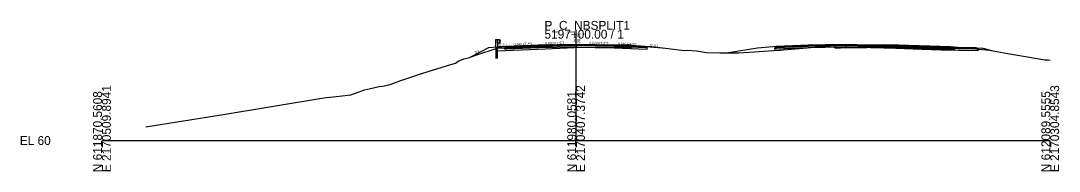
# Model space of a CAD drawing. Extents: x -26 to 1303, y -3010 to 12038.
# Drawn here: x -25.7 to 302.8, y 11990.3 to 12037.8 of the extents above; entities that cross this region are included whole.
import ezdxf

# ---------------------------------------------------------------- set-up
doc = ezdxf.new("R2010")
doc.units = 0
for name, color, linetype in [('RD_GPK_XS_Cell', 7, 'Continuous'), ('RD_PD_Final_TrvlWay', 7, 'Continuous'), ('RD_XS_Base', 7, 'Continuous'), ('RD_XS_ExGround', 7, 'Continuous'), ('RD_XS_ExPaveRet', 7, 'Continuous'), ('RD_XS_GR', 7, 'Continuous'), ('RD_XS_Greenside', 7, 'Continuous'), ('RD_XS_Pave', 7, 'Continuous'), ('RD_XS_PaveOvlay_CP', 7, 'Continuous'), ('RD_XS_TieSlope', 7, 'Continuous'), ('RD_XS_TX_Elev_EX', 7, 'Continuous'), ('RD_XS_TX_Elev_PR', 7, 'Continuous'), ('RD_XS_TX_ShdSlope', 7, 'Continuous'), ('RD_XS_TX_Slope', 7, 'Continuous')]:
    doc.layers.add(name, color=color, linetype=linetype)

msp = doc.modelspace()

# ---------------------------------------------------------------- linework, layer by layer
at = {"layer": 'RD_GPK_XS_Cell'}
for p, q in [((150, 12000), (150, 12035)), ((0, 12000), (150, 12000)), ((150, 12000), (300, 12000))]:
    msp.add_line(p, q, dxfattribs=at)
at = {"layer": 'RD_PD_Final_TrvlWay'}
for p, q in [((125.14, 12029.49), (124.64, 12029.45)), ((124.64, 12029.45), (124.64, 12025.88)), ((125.14, 12025.88), (125.14, 12029.49))]:
    msp.add_line(p, q, dxfattribs=at)
at = {"layer": 'RD_XS_Base'}
for p, q in [((127.5, 12029.38), (128, 12029.4)), ((127.5, 12028.88), (127.5, 12029.38)), ((127.5, 12029.38), (127.5, 12029.38)), ((128, 12028.9), (127.5, 12028.88)), ((127.5, 12028.88), (127.5, 12028.88)), ((127.5, 12028.88), (127.5, 12028.88)), ((128, 12029.4), (138, 12029.8)), ((128, 12029.4), (128, 12029.4)), ((138, 12029.3), (128, 12028.9)), ((128, 12028.9), (128, 12028.9)), ((138, 12029.8), (150, 12030.04)), ((138, 12029.8), (138, 12029.8)), ((150, 12029.54), (138, 12029.3)), ((138, 12029.3), (138, 12029.3)), ((150, 12030.04), (150, 12030.2)), ((150, 12030.2), (150, 12029.54)), ((150, 12030.04), (150, 12029.54)), ((162, 12029.8), (150, 12030.04)), ((150, 12030.04), (150, 12030.04)), ((150, 12029.54), (150, 12029.54)), ((150, 12029.54), (150, 12029.54)), ((150, 12029.54), (162, 12029.3)), ((172, 12029.4), (162, 12029.8)), ((162, 12029.3), (172.5, 12028.88)), ((164, 12029.72), (164, 12029.72)), ((164, 12029.22), (164, 12029.22)), ((172.5, 12029.38), (172, 12029.4)), ((172, 12029.4), (172, 12029.4)), ((172.5, 12028.88), (172.5, 12029.38)), ((172.5, 12029.38), (172.5, 12029.38)), ((172.5, 12028.88), (172.5, 12028.88)), ((172.5, 12028.88), (172.5, 12028.88)), ((212.86, 12029.38), (213.25, 12029.4)), ((212.86, 12029.27), (212.86, 12029.38)), ((212.86, 12028.88), (212.86, 12029.27)), ((213.25, 12028.9), (212.86, 12028.88)), ((213.25, 12029.4), (213.36, 12029.4)), ((213.36, 12028.9), (213.25, 12028.9)), ((213.36, 12029.4), (220.94, 12029.71)), ((220.94, 12029.21), (213.36, 12028.9)), ((220.94, 12029.71), (223.36, 12029.8)), ((223.36, 12029.3), (220.94, 12029.21)), ((223.36, 12029.8), (228.76, 12029.91)), ((228.76, 12029.41), (223.36, 12029.3)), ((228.76, 12029.91), (235.36, 12030.04)), ((235.36, 12029.54), (228.76, 12029.41)), ((235.36, 12030.16), (235.36, 12030.2)), ((235.36, 12030.2), (235.36, 12030.01)), ((235.36, 12030.04), (235.36, 12030.16)), ((235.36, 12030.04), (235.36, 12030.04)), ((238.87, 12029.97), (235.36, 12030.04)), ((235.36, 12030.04), (235.36, 12030.04)), ((235.36, 12030.04), (235.36, 12029.9)), ((235.36, 12030.01), (235.36, 12029.54)), ((235.36, 12029.9), (235.36, 12029.54)), ((235.36, 12029.54), (238.87, 12029.47)), ((247.36, 12029.8), (238.87, 12029.97)), ((238.87, 12029.47), (247.36, 12029.3)), ((251.11, 12029.66), (247.36, 12029.8)), ((247.36, 12029.3), (251.11, 12029.16)), ((259.37, 12029.33), (251.11, 12029.66)), ((251.11, 12029.16), (259.37, 12028.83)), ((265.17, 12029.21), (259.37, 12029.33)), ((259.37, 12028.83), (265.34, 12028.71)), ((276.67, 12028.98), (265.17, 12029.21)), ((265.34, 12028.71), (277.17, 12028.47)), ((276.84, 12028.98), (276.67, 12028.98)), ((277.17, 12028.97), (276.84, 12028.98)), ((277.17, 12028.79), (277.17, 12028.97)), ((277.17, 12028.47), (277.17, 12028.79))]:
    msp.add_line(p, q, dxfattribs=at)
at = {"layer": 'RD_XS_ExGround'}
msp.add_lwpolyline([(13.83, 12004.3), (37.72, 12008.08), (70.17, 12013.47), (75, 12014.04), (78.77, 12014.48), (80.21, 12014.96), (83.07, 12016.05), (84.92, 12016.48), (87.72, 12017.07), (88.89, 12017.23), (91.14, 12017.73), (94.19, 12018.84), (98.32, 12020.24), (101.09, 12021.2), (101.19, 12021.2), (104.83, 12022.32), (108.64, 12023.52), (109.29, 12023.75), (111.88, 12024.47), (112.64, 12025.04), (114.44, 12025.83), (115.91, 12026.14), (118, 12026.91), (125.01, 12029.15), (140.16, 12029.77), (151.86, 12030.25), (161.97, 12030.16), (167.52, 12030.1), (171.81, 12029.79), (175.64, 12029.5), (180.84, 12028.83), (184.15, 12028.5), (185.23, 12028.57), (188.07, 12028.36), (191.22, 12027.79), (195.47, 12027.75), (201.42, 12027.67), (206.46, 12028.03), (212.45, 12028.41), (214.01, 12028.51), (214.64, 12028.58), (215.48, 12028.63), (231.89, 12030), (239.22, 12030.13), (247.19, 12030.27), (269.5, 12029.54), (269.63, 12029.53), (269.71, 12029.52), (269.85, 12029.51), (270.37, 12029.47), (280.92, 12028.54), (281.95, 12028.33), (286.58, 12027.5), (292.13, 12026.57), (298.33, 12025.5), (299.34, 12025.48), (300, 12025.37)], dxfattribs=at)
at = {"layer": 'RD_XS_ExPaveRet'}
for p, q in [((140.16, 12029.77), (125.01, 12029.15)), ((151.86, 12030.25), (140.16, 12029.77)), ((161.97, 12030.16), (151.86, 12030.25)), ((167.52, 12030.1), (161.97, 12030.16)), ((233.66, 12030.03), (231.89, 12030)), ((239.22, 12030.13), (233.66, 12030.03)), ((269.63, 12029.53), (269.5, 12029.54))]:
    msp.add_line(p, q, dxfattribs=at)
for points in [[(161.97, 12030.16), (151.86, 12030.25), (151.86, 12030.25), (151.86, 12030.25), (140.16, 12029.77), (140.16, 12029.77), (125.01, 12029.15), (125.01, 12028.4), (125.01, 12028.4), (140.16, 12029.02), (140.16, 12029.02), (151.86, 12029.5), (151.86, 12029.5), (151.86, 12029.5), (161.97, 12029.41), (161.97, 12029.41), (167.52, 12029.35), (167.52, 12029.35), (167.52, 12030.1), (161.97, 12030.16), (161.97, 12030.16)], [(125.01, 12029.15), (125.01, 12028.4), (140.16, 12029.02), (151.86, 12029.5), (161.97, 12029.41), (167.52, 12029.35), (167.52, 12030.1)], [(269.63, 12029.53), (269.63, 12029.53), (269.63, 12029.4), (269.63, 12028.78), (269.63, 12028.78), (269.63, 12028.78), (268.87, 12028.81), (268.42, 12028.82), (251.96, 12029.36), (247.19, 12029.52), (241.96, 12029.43), (239.22, 12029.38), (233.66, 12029.28), (231.89, 12029.25), (231.89, 12029.25), (231.89, 12029.5), (231.89, 12030), (231.89, 12030), (233.66, 12030.03), (239.22, 12030.13), (241.96, 12030.18), (247.19, 12030.27), (251.96, 12030.11), (268.42, 12029.57), (268.87, 12029.56), (269.63, 12029.53), (269.63, 12029.53)], [(231.89, 12030), (231.89, 12029.5), (231.89, 12029.25), (233.66, 12029.28), (239.22, 12029.38), (241.96, 12029.43), (247.19, 12029.52), (251.96, 12029.36), (268.42, 12028.82), (268.87, 12028.81), (269.63, 12028.78), (269.63, 12028.78), (269.63, 12029.4), (269.63, 12029.53), (269.63, 12029.53)], [(269.5, 12029.54), (268.42, 12029.57), (251.96, 12030.11), (247.19, 12030.27), (241.96, 12030.18), (239.22, 12030.13)]]:
    msp.add_lwpolyline(points, dxfattribs=at)
at = {"layer": 'RD_XS_GR'}
for points in [[(125.14, 12031.88), (125.14, 12029.49), (124.64, 12029.45), (124.64, 12031.88), (124.89, 12031.88), (125.14, 12031.88)], [(125.81, 12031.88), (125.81, 12030.72), (125.14, 12030.72), (125.14, 12031.88), (125.81, 12031.88)], [(126.08, 12031.59), (125.81, 12031.88), (125.81, 12030.72), (125.81, 12030.72), (125.81, 12030.72), (126.08, 12031.01), (126.08, 12031.01), (125.81, 12031.3), (125.81, 12031.3), (126.08, 12031.59), (126.08, 12031.59)]]:
    msp.add_lwpolyline(points, dxfattribs=at)
at = {"layer": 'RD_XS_Greenside'}
for p, q in [((122.33, 12029.26), (116.57, 12026.38)), ((207.36, 12029.24), (198.2, 12027.71)), ((278.67, 12029.14), (281.49, 12028.43))]:
    msp.add_line(p, q, dxfattribs=at)
at = {"layer": 'RD_XS_Pave'}
for p, q in [((138, 12030.12), (128, 12029.72)), ((138, 12029.96), (128, 12029.56)), ((128, 12029.56), (138, 12029.96)), ((128, 12029.4), (138, 12029.8)), ((128, 12029.72), (128, 12029.72)), ((128, 12029.72), (128, 12029.56)), ((128, 12029.56), (128, 12029.56)), ((128, 12029.56), (128, 12029.4)), ((128, 12029.56), (128, 12029.56)), ((128, 12029.56), (128, 12029.56)), ((128, 12029.4), (128, 12029.4)), ((128, 12029.4), (128, 12029.4)), ((150, 12030.36), (138, 12030.12)), ((150, 12030.2), (138, 12029.96)), ((138, 12029.96), (150, 12030.2)), ((138, 12030.12), (138, 12030.12)), ((138, 12029.8), (150, 12030.04)), ((138, 12029.96), (138, 12029.96)), ((138, 12029.96), (138, 12029.96)), ((138, 12029.8), (138, 12029.8)), ((162, 12030.12), (150, 12030.36)), ((150, 12030.04), (150, 12030.2)), ((150, 12030.2), (162, 12029.96)), ((162, 12029.96), (150, 12030.2)), ((150, 12030.2), (150, 12030.04)), ((150, 12030.04), (150, 12030.04)), ((150, 12030.04), (150, 12030.04)), ((150, 12030.04), (162, 12029.8)), ((172, 12029.72), (162, 12030.12)), ((162, 12029.96), (172, 12029.56)), ((172, 12029.56), (162, 12029.96)), ((162, 12029.8), (172, 12029.4)), ((164, 12030.04), (164, 12030.04)), ((164, 12029.88), (164, 12029.88)), ((164, 12029.88), (164, 12029.88)), ((164, 12029.72), (164, 12029.72)), ((172, 12029.56), (172, 12029.72)), ((172, 12029.72), (172, 12029.72)), ((172, 12029.56), (172, 12029.56)), ((172, 12029.56), (172, 12029.56)), ((172, 12029.4), (172, 12029.56)), ((172, 12029.56), (172, 12029.56)), ((172, 12029.4), (172, 12029.4)), ((172, 12029.4), (172, 12029.4)), ((220.94, 12030.03), (213.36, 12029.72)), ((220.94, 12029.87), (213.36, 12029.56)), ((213.36, 12029.56), (220.94, 12029.87)), ((213.36, 12029.72), (213.36, 12029.69)), ((213.36, 12029.4), (220.94, 12029.71)), ((213.36, 12029.69), (213.36, 12029.56)), ((213.36, 12029.56), (213.36, 12029.53)), ((213.36, 12029.53), (213.36, 12029.4)), ((223.36, 12030.12), (220.94, 12030.03)), ((223.36, 12029.96), (220.94, 12029.87)), ((220.94, 12029.87), (223.36, 12029.96)), ((220.94, 12029.71), (223.36, 12029.8)), ((228.76, 12030.23), (223.36, 12030.12)), ((228.76, 12030.07), (223.36, 12029.96)), ((223.36, 12029.96), (228.76, 12030.07)), ((223.36, 12029.8), (228.76, 12029.91)), ((235.36, 12030.36), (228.76, 12030.23)), ((235.36, 12030.2), (228.76, 12030.07)), ((228.76, 12030.07), (235.36, 12030.2)), ((228.76, 12029.91), (235.36, 12030.04)), ((238.87, 12030.29), (235.36, 12030.36)), ((235.36, 12030.16), (235.36, 12030.2)), ((235.36, 12030.2), (238.87, 12030.13)), ((238.87, 12030.13), (235.36, 12030.2)), ((235.36, 12030.2), (235.36, 12030.2)), ((235.36, 12030.2), (235.36, 12030.2)), ((235.36, 12030.2), (235.36, 12030.16)), ((235.36, 12030.04), (235.36, 12030.16)), ((235.36, 12030.16), (235.36, 12030.04)), ((235.36, 12030.04), (235.36, 12030.04)), ((235.36, 12030.04), (235.36, 12030.04)), ((235.36, 12030.04), (238.87, 12029.97)), ((247.36, 12030.12), (238.87, 12030.29)), ((238.87, 12030.13), (247.36, 12029.96)), ((247.36, 12029.96), (238.87, 12030.13)), ((238.87, 12029.97), (247.36, 12029.8)), ((251.11, 12029.97), (247.36, 12030.12)), ((247.36, 12029.96), (251.11, 12029.81)), ((251.11, 12029.81), (247.36, 12029.96)), ((247.36, 12029.8), (251.11, 12029.66)), ((259.37, 12029.64), (251.11, 12029.97)), ((251.11, 12029.81), (259.37, 12029.48)), ((259.37, 12029.48), (251.11, 12029.81)), ((251.11, 12029.66), (259.37, 12029.33)), ((265.17, 12029.53), (259.37, 12029.64)), ((259.37, 12029.48), (265.17, 12029.37)), ((265.17, 12029.37), (259.37, 12029.48)), ((259.37, 12029.33), (265.17, 12029.21)), ((276.67, 12029.3), (265.17, 12029.53)), ((265.17, 12029.37), (276.67, 12029.14)), ((276.67, 12029.14), (265.17, 12029.37)), ((265.17, 12029.21), (276.67, 12028.98)), ((276.67, 12029.24), (276.67, 12029.3)), ((276.67, 12029.14), (276.67, 12029.24)), ((276.67, 12029.08), (276.67, 12029.14)), ((276.67, 12028.98), (276.67, 12029.08))]:
    msp.add_line(p, q, dxfattribs=at)
at = {"layer": 'RD_XS_PaveOvlay_CP'}
for p, q in [((128, 12029.72), (138, 12030.12)), ((138, 12030.12), (150, 12030.36)), ((150, 12030.36), (162, 12030.12)), ((162, 12030.12), (172, 12029.72)), ((220.94, 12030.03), (213.36, 12029.72)), ((223.36, 12030.12), (220.94, 12030.03)), ((228.76, 12030.23), (223.36, 12030.12)), ((235.36, 12030.36), (228.76, 12030.23)), ((238.87, 12030.29), (235.36, 12030.36)), ((247.36, 12030.12), (238.87, 12030.29)), ((251.11, 12029.97), (247.36, 12030.12)), ((259.37, 12029.64), (251.11, 12029.97)), ((265.17, 12029.53), (259.37, 12029.64)), ((276.67, 12029.3), (265.17, 12029.53))]:
    msp.add_line(p, q, dxfattribs=at)
at = {"layer": 'RD_XS_TieSlope'}
for p, q in [((128, 12029.72), (122.33, 12029.26)), ((172, 12029.72), (177.19, 12029.3)), ((213.36, 12029.72), (207.36, 12029.24)), ((276.67, 12029.3), (278.67, 12029.14))]:
    msp.add_line(p, q, dxfattribs=at)

# ---------------------------------------------------------------- texts
at = {"layer": 'RD_GPK_XS_Cell'}
for s, p in [('P_C_NBSPLIT1', (140, 12035)), ('5197+00.00 / 1', (140, 12032.2)), ('EL 60', (-26, 11998.6))]:
    msp.add_text(s, height=2.8, dxfattribs=at).set_placement(p)
for s, p in [('N 611870.5608', (0, 11990)), ('E 2170509.8941', (2.8, 11990)), ('N 611980.0581', (150, 11990)), ('E 2170407.3742', (152.8, 11990)), ('N 612089.5555', (300, 11990)), ('E 2170304.8543', (302.8, 11990))]:
    msp.add_text(s, height=2.8, rotation=90, dxfattribs=at).set_placement(p)
at = {"layer": 'RD_XS_TX_Elev_EX'}
msp.add_text('90.17', height=0.6, rotation=90, dxfattribs=at).set_placement((149.78, 12031.09))
at = {"layer": 'RD_XS_TX_Elev_PR'}
msp.add_text('90.36', height=1, rotation=90, dxfattribs=at).set_placement((151.33, 12030.65))
at = {"layer": 'RD_XS_TX_ShdSlope'}
for rotation, p in [(4.5739, (125.35, 12029.73)), (355.4261, (173.06, 12029.82))]:
    msp.add_text('12.5:1', height=0.75, rotation=rotation, dxfattribs=at).set_placement(p)
at = {"layer": 'RD_XS_TX_Slope'}
for s, rotation, p in [('0.040 FT./FT.', 2.2906, (130.25, 12029.99)), ('0.020 FT./FT.', 1.1458, (140.25, 12030.35)), ('0.020 FT./FT.', 358.8542, (154.19, 12030.47)), ('0.040 FT./FT.', 357.7094, (163.26, 12030.25)), ('2:1', 26.5651, (118.2, 12027.49))]:
    msp.add_text(s, height=0.75, rotation=rotation, dxfattribs=at).set_placement(p)

doc.saveas('drawing.dxf')
